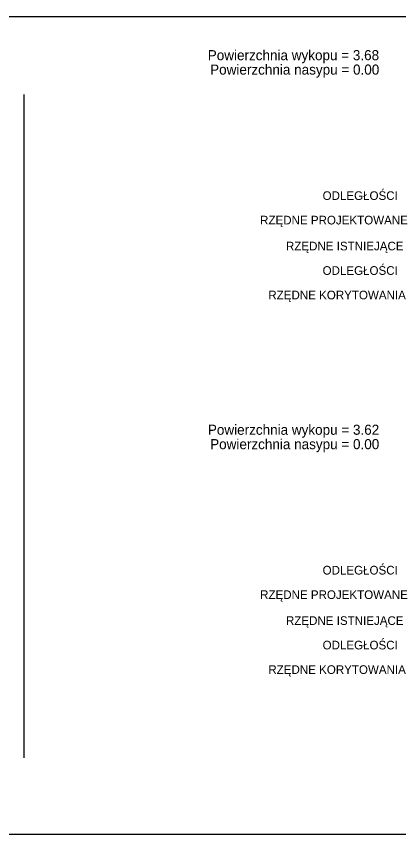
# Model space of a CAD drawing. Extents: x 7492871 to 7493499, y 5802964 to 5802992.
# Drawn here: x 7493229.66 to 7493242.92, y 5802963.88 to 5802992.28 of the extents above; entities that cross this region are included whole.
import ezdxf

# ---------------------------------------------------------------- set-up
doc = ezdxf.new("R2010")
doc.units = 0
for name, color, linetype in [('_wydruk', 7, 'Continuous'), ('d_pop_nasyp_opis', 7, 'Continuous'), ('d_pop_wykop_opis', 7, 'Continuous'), ('opisy_ramki_pop', 7, 'Continuous'), ('pop_opis', 7, 'Continuous')]:
    doc.layers.add(name, color=color, linetype=linetype)

msp = doc.modelspace()

# ---------------------------------------------------------------- linework, layer by layer
at = {"layer": '_wydruk'}
msp.add_lwpolyline([(7492871.369, 5802992.281), (7493499.283, 5802992.281), (7493499.283, 5802963.881), (7492871.369, 5802963.881)], close=True, dxfattribs=at)
at = {"layer": 'opisy_ramki_pop'}
msp.add_line((7493229.921, 5802989.573), (7493229.921, 5802966.547), dxfattribs=at)

# ---------------------------------------------------------------- texts
at = {"layer": 'd_pop_nasyp_opis'}
for p in [(7493236.382, 5802990.259), (7493236.382, 5802977.259)]:
    msp.add_text('Powierzchnia nasypu = 0.00', height=0.35, dxfattribs=at).set_placement(p)
at = {"layer": 'd_pop_wykop_opis'}
for s, p in [('Powierzchnia wykopu = 3.68', (7493236.299, 5802990.759)), ('Powierzchnia wykopu = 3.62', (7493236.303, 5802977.759))]:
    msp.add_text(s, height=0.35, dxfattribs=at).set_placement(p)
at = {"layer": 'pop_opis'}
for s, p in [('ODLEGŁOŚCI', (7493240.283, 5802985.909)), ('ODLEGŁOŚCI', (7493240.283, 5802985.909)), ('ODLEGŁOŚCI', (7493240.283, 5802985.909)), ('ODLEGŁOŚCI', (7493240.283, 5802985.909)), ('RZĘDNE PROJEKTOWANE', (7493238.115, 5802985.059)), ('RZĘDNE PROJEKTOWANE', (7493238.115, 5802985.059)), ('RZĘDNE PROJEKTOWANE', (7493238.115, 5802985.059)), ('RZĘDNE PROJEKTOWANE', (7493238.115, 5802985.059)), ('RZĘDNE ISTNIEJĄCE', (7493239.012, 5802984.159)), ('ODLEGŁOŚCI', (7493240.283, 5802983.309)), ('RZĘDNE KORYTOWANIA', (7493238.401, 5802982.459)), ('ODLEGŁOŚCI', (7493240.283, 5802972.909)), ('ODLEGŁOŚCI', (7493240.283, 5802972.909)), ('ODLEGŁOŚCI', (7493240.283, 5802972.909)), ('ODLEGŁOŚCI', (7493240.283, 5802972.909)), ('RZĘDNE PROJEKTOWANE', (7493238.115, 5802972.059)), ('RZĘDNE PROJEKTOWANE', (7493238.115, 5802972.059)), ('RZĘDNE PROJEKTOWANE', (7493238.115, 5802972.059)), ('RZĘDNE PROJEKTOWANE', (7493238.115, 5802972.059)), ('RZĘDNE ISTNIEJĄCE', (7493239.012, 5802971.159)), ('ODLEGŁOŚCI', (7493240.283, 5802970.309)), ('RZĘDNE KORYTOWANIA', (7493238.401, 5802969.459))]:
    msp.add_text(s, height=0.3, dxfattribs=at).set_placement(p)

doc.saveas('drawing.dxf')
